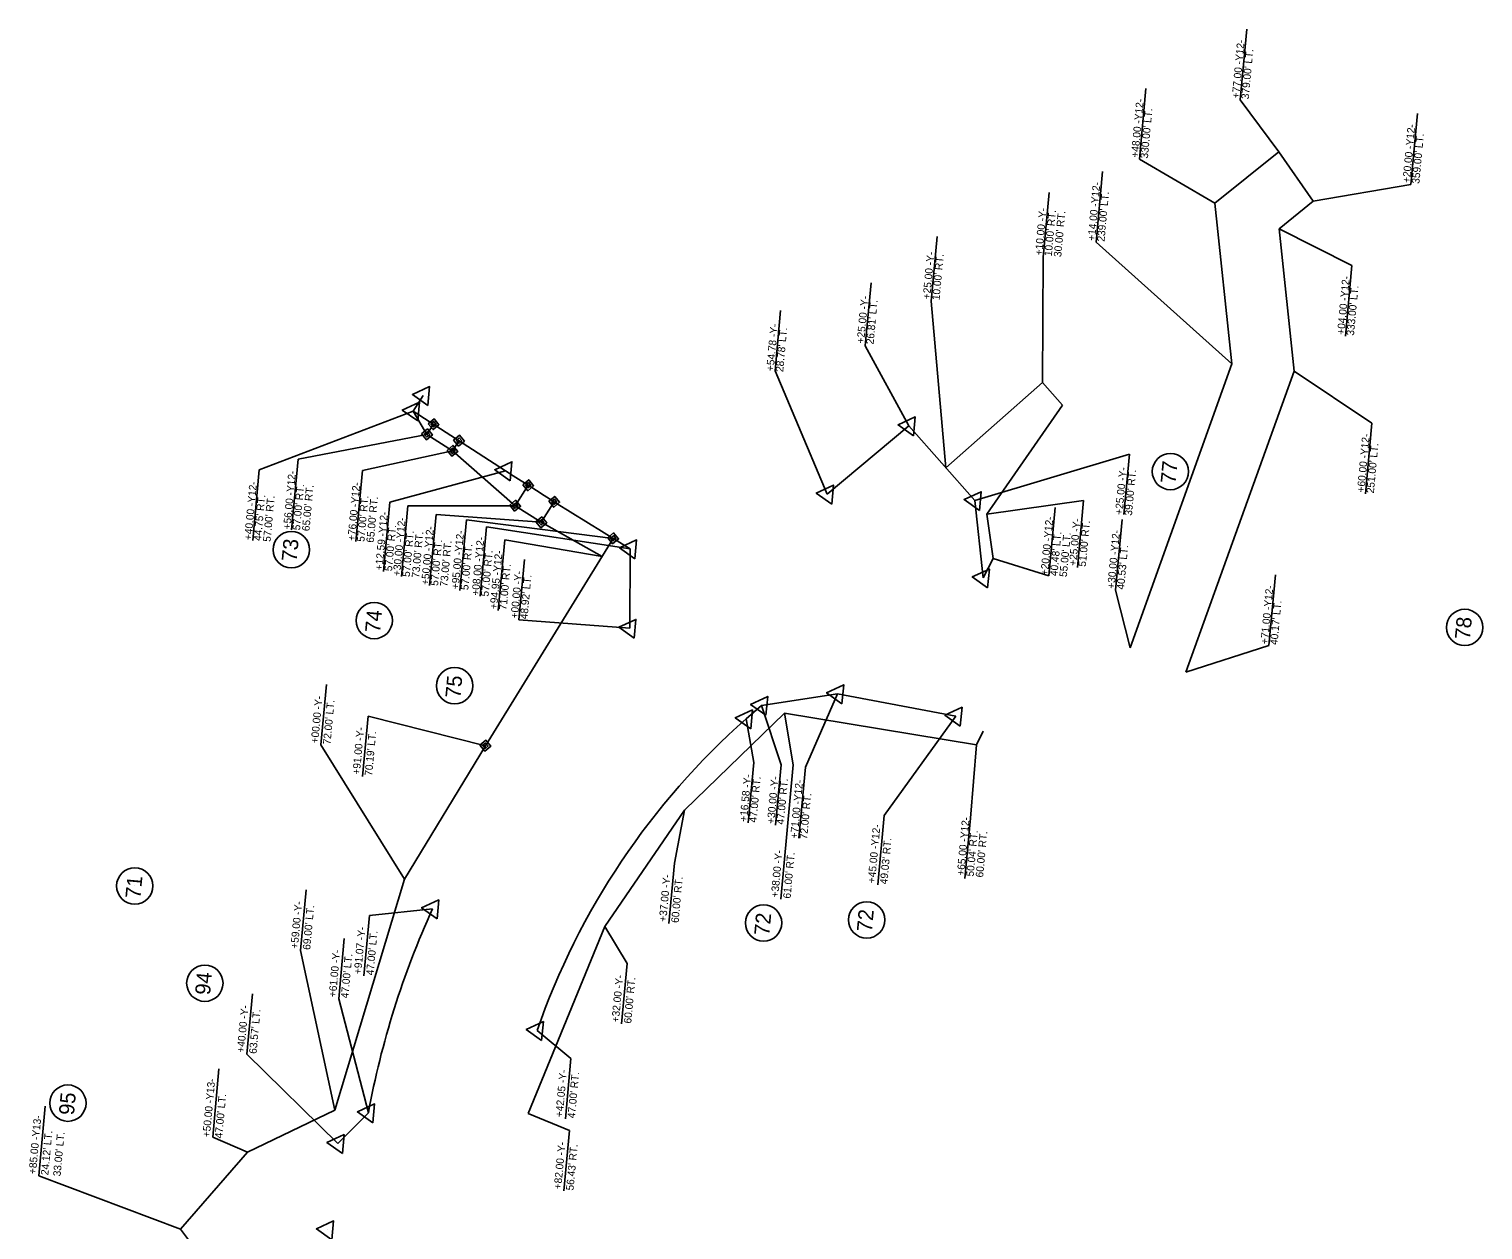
# Model space of a CAD drawing. Extents: x 2010883 to 2014849, y 442000 to 447413.
# Drawn here: x 2012385 to 2013345, y 446621 to 447413 of the extents above; entities that cross this region are included whole.
import ezdxf

# ---------------------------------------------------------------- set-up
doc = ezdxf.new("R2010")
doc.units = 0
for name, color, linetype in [('Prop Easement Construction', 7, 'Continuous'), ('Prop Easement Construction Station Offsets', 7, 'Continuous'), ('Prop Easement Permanent Drainage', 7, 'Continuous'), ('Prop Easement Permanent Drainage Station Offsets', 7, 'Continuous'), ('Prop Easement Permanent Drainage Utility', 7, 'Continuous'), ('Prop Easement Permanent Drainage Utility Station Offsets', 7, 'Continuous'), ('Prop Parcel Number CELL', 7, 'Continuous'), ('Prop Parcel Number Text', 7, 'Continuous'), ('Prop ROW Marker CELL', 7, 'Continuous'), ('Prop ROW Permanent Easement CELL', 7, 'Continuous'), ('Prop ROW RW Lines', 7, 'Continuous'), ('Prop ROW Station Offsets', 7, 'Continuous')]:
    doc.layers.add(name, color=color, linetype=linetype)

msp = doc.modelspace()

# ---------------------------------------------------------------- linework, layer by layer
at = {"layer": 'Prop Easement Construction'}
for p, q in [((2012990.29, 447123.69), (2013054.01, 447179.95)), ((2013067.24, 447164.96), (2013054.01, 447179.95)), ((2012647.94, 447145.67), (2012638.85, 447161.07)), ((2013017.43, 447092.96), (2013067.24, 447164.96)), ((2012706.1, 447098.62), (2012664.74, 447134.81)), ((2013021.47, 447063.84), (2013017.43, 447092.96)), ((2012763.43, 447065.14), (2012723.36, 447087.67)), ((2013014.83, 447050.93), (2013021.47, 447063.84)), ((2012817.86, 446897.73), (2012883.87, 446961.68)), ((2012883.87, 446961.68), (2013010.5, 446940.82)), ((2013010.5, 446940.82), (2013014.83, 446949.79)), ((2012633.05, 446852.19), (2012686.46, 446940.24)), ((2012765.26, 446820.94), (2012817.86, 446897.73)), ((2012587.22, 446699.78), (2012633.05, 446852.19)), ((2012714.74, 446697.6), (2012765.26, 446820.94)), ((2012529.44, 446672.19), (2012587.22, 446699.78)), ((2012485.28, 446621.31), (2012529.44, 446672.19)), ((2012490.71, 446614.28), (2012485.28, 446621.31))]:
    msp.add_line(p, q, dxfattribs=at)
at = {"layer": 'Prop Easement Construction Station Offsets'}
for p, q in [((2013054.57, 447262.58), (2013058.49, 447305.26)), ((2012980.52, 447233.54), (2012984.45, 447276.23)), ((2013054.01, 447179.95), (2013054.57, 447262.58)), ((2012990.29, 447123.69), (2012980.52, 447233.54)), ((2013017.43, 447092.96), (2013081.16, 447102.05)), ((2013077.08, 447057.77), (2013081.16, 447102.05)), ((2012695.02, 447029.42), (2012699.31, 447076.07)), ((2012763.43, 447065.14), (2012699.31, 447076.07)), ((2012577.95, 446940.74), (2012581.61, 446980.57)), ((2012883.87, 446961.68), (2012889.62, 446927.71)), ((2012577.95, 446940.74), (2012633.05, 446852.19)), ((2013010.5, 446940.82), (2013006.51, 446892.51)), ((2012881.48, 446839.09), (2012889.62, 446927.71)), ((2012817.86, 446897.73), (2012811.26, 446862.87)), ((2013002.85, 446852.68), (2013006.51, 446892.51)), ((2012807.6, 446823.03), (2012811.26, 446862.87)), ((2012564.54, 446805.26), (2012568.21, 446845.1)), ((2012765.26, 446820.94), (2012780.02, 446796.52)), ((2012564.54, 446805.26), (2012587.22, 446699.78)), ((2012776.35, 446756.69), (2012780.02, 446796.52)), ((2012506.59, 446682.04), (2012510.72, 446727)), ((2012391.77, 446656.58), (2012395.98, 446702.39)), ((2012714.74, 446697.6), (2012741.93, 446686.34)), ((2012529.44, 446672.19), (2012506.59, 446682.04)), ((2012738.27, 446646.51), (2012741.93, 446686.34)), ((2012485.28, 446621.31), (2012391.77, 446656.58))]:
    msp.add_line(p, q, dxfattribs=at)
at = {"layer": 'Prop Easement Permanent Drainage'}
for p, q in [((2013167.64, 447298.11), (2013209.93, 447332.06)), ((2013232.57, 447299.63), (2013209.93, 447332.06)), ((2013178.99, 447192.14), (2013167.64, 447298.11)), ((2013210.12, 447281.23), (2013232.57, 447299.63)), ((2013220.18, 447187.34), (2013210.12, 447281.23)), ((2013111.91, 447004.78), (2013178.99, 447192.14)), ((2013148.65, 446988.76), (2013220.18, 447187.34)), ((2012652.28, 447152.39), (2012647.94, 447145.67)), ((2012664.74, 447134.81), (2012647.94, 447145.67)), ((2012664.74, 447134.81), (2012669.08, 447141.53)), ((2012706.1, 447098.62), (2012714.71, 447112.1)), ((2012723.36, 447087.67), (2012706.1, 447098.62)), ((2012731.89, 447101.2), (2012723.36, 447087.67))]:
    msp.add_line(p, q, dxfattribs=at)
at = {"layer": 'Prop Easement Permanent Drainage Station Offsets'}
for p, q in [((2013184.54, 447366.35), (2013188.83, 447413.07)), ((2013117.96, 447327.24), (2013122.26, 447373.96)), ((2013209.93, 447332.06), (2013184.54, 447366.35)), ((2013297.08, 447310.56), (2013301.38, 447357.28)), ((2013167.64, 447298.11), (2013117.96, 447327.24)), ((2013089.35, 447272.38), (2013093.64, 447319.11)), ((2013232.57, 447299.63), (2013297.08, 447310.56)), ((2013210.12, 447281.23), (2013258.22, 447257.12)), ((2013178.99, 447192.14), (2013089.35, 447272.38)), ((2013253.92, 447210.39), (2013258.22, 447257.12)), ((2013271.37, 447153.08), (2013220.18, 447187.34)), ((2013267.07, 447106.36), (2013271.37, 447153.08)), ((2012562.93, 447129.4), (2012647.94, 447145.67)), ((2012605.39, 447121.8), (2012664.74, 447134.81)), ((2012558.63, 447082.6), (2012562.93, 447129.4)), ((2012601.09, 447075), (2012605.39, 447121.8)), ((2012631.03, 447051.83), (2012635.33, 447098.63)), ((2012635.33, 447098.63), (2012706.1, 447098.62)), ((2012649.69, 447045.94), (2012654, 447092.74)), ((2012654, 447092.74), (2012723.36, 447087.67)), ((2013102.31, 447042.81), (2013106.6, 447089.53)), ((2013203.47, 447006.29), (2013207.77, 447053.01)), ((2013102.31, 447042.81), (2013111.91, 447004.78)), ((2013203.47, 447006.29), (2013148.65, 446988.76))]:
    msp.add_line(p, q, dxfattribs=at)
at = {"layer": 'Prop Easement Permanent Drainage Utility'}
msp.add_line((2012686.46, 446940.24), (2012770.77, 447077.06), dxfattribs=at)
at = {"layer": 'Prop Easement Permanent Drainage Utility Station Offsets'}
for p, q in [((2012669.68, 447042.71), (2012673.97, 447089.31)), ((2012770.77, 447077.06), (2012673.97, 447089.31)), ((2012605.39, 446919.89), (2012609.06, 446959.72)), ((2012609.06, 446959.72), (2012686.46, 446940.24))]:
    msp.add_line(p, q, dxfattribs=at)
at = {"layer": 'Prop Parcel Number CELL'}
for p, q in [((2013138.47, 447121.13), (2013138.47, 447121.13)), ((2012558.46, 447069.57), (2012558.46, 447069.57)), ((2012613.15, 447022.83), (2012613.15, 447022.83)), ((2013332.62, 447018.29), (2013332.62, 447018.29)), ((2012666.19, 446979.87), (2012666.19, 446979.87)), ((2012455.16, 446847.72), (2012455.16, 446847.72)), ((2012938.05, 446825.33), (2012938.05, 446825.33)), ((2012870, 446823.3), (2012870, 446823.3)), ((2012501.39, 446783.56), (2012501.39, 446783.56)), ((2012411.03, 446704.44), (2012411.03, 446704.44))]:
    msp.add_line(p, q, dxfattribs=at)
for centre in [(2013138.47, 447121.13), (2012558.46, 447069.57), (2012613.15, 447022.83), (2013332.62, 447018.29), (2012666.19, 446979.87), (2012455.16, 446847.72), (2012870, 446823.3), (2012938.05, 446825.33), (2012501.39, 446783.56), (2012411.03, 446704.44)]:
    msp.add_circle(centre, 12, dxfattribs=at)
at = {"layer": 'Prop ROW Marker CELL'}
for p, q in [((2012645.49, 447171.36), (2012645.49, 447171.36)), ((2012638.85, 447161.07), (2012638.85, 447161.07)), ((2012652.28, 447152.39), (2012652.28, 447152.39)), ((2012965.93, 447151.28), (2012965.93, 447151.28)), ((2012647.94, 447145.67), (2012647.94, 447145.67)), ((2012669.08, 447141.53), (2012669.08, 447141.53)), ((2012664.74, 447134.81), (2012664.74, 447134.81)), ((2012699.82, 447121.67), (2012699.82, 447121.67)), ((2012714.71, 447112.1), (2012714.71, 447112.1)), ((2012911.99, 447106.28), (2012911.99, 447106.28)), ((2013009.49, 447101.95), (2013009.49, 447101.95)), ((2012706.1, 447098.62), (2012706.1, 447098.62)), ((2012731.89, 447101.2), (2012731.89, 447101.2)), ((2012723.36, 447087.67), (2012723.36, 447087.67)), ((2012770.77, 447077.06), (2012770.77, 447077.06)), ((2012782.07, 447070.18), (2012782.07, 447070.18)), ((2013014.83, 447050.93), (2013014.83, 447050.93)), ((2012781.69, 447017.72), (2012781.69, 447017.72)), ((2012918.75, 446974.55), (2012918.75, 446974.55)), ((2012858.55, 446958), (2012858.55, 446958)), ((2012868.61, 446966.88), (2012868.61, 446966.88)), ((2012996.81, 446959.74), (2012996.81, 446959.74)), ((2012686.46, 446940.24), (2012686.46, 446940.24)), ((2012651.56, 446832.67), (2012651.56, 446832.67)), ((2012720.57, 446752.32), (2012720.57, 446752.32)), ((2012609.26, 446698), (2012609.26, 446698)), ((2012589.14, 446677.83), (2012589.14, 446677.83)), ((2012582.19, 446620.8), (2012582.19, 446620.8))]:
    msp.add_line(p, q, dxfattribs=at)
for points in [[(2012648.51, 447164.8), (2012638.32, 447172.02), (2012649.65, 447177.25)], [(2012641.86, 447154.52), (2012631.68, 447161.73), (2012643, 447166.96)], [(2012968.94, 447144.73), (2012958.76, 447151.94), (2012970.08, 447157.18)], [(2012702.83, 447115.12), (2012692.65, 447122.33), (2012703.97, 447127.57)], [(2012915, 447099.73), (2012904.82, 447106.94), (2012916.14, 447112.18)], [(2013012.5, 447095.4), (2013002.32, 447102.61), (2013013.64, 447107.85)], [(2012785.08, 447063.63), (2012774.9, 447070.84), (2012786.23, 447076.08)], [(2013017.84, 447044.38), (2013007.66, 447051.59), (2013018.99, 447056.83)], [(2012784.7, 447011.16), (2012774.52, 447018.37), (2012785.84, 447023.61)], [(2012921.76, 446967.99), (2012911.58, 446975.2), (2012922.91, 446980.44)], [(2012871.62, 446960.33), (2012861.44, 446967.54), (2012872.77, 446972.78)], [(2012861.56, 446951.44), (2012851.38, 446958.66), (2012862.71, 446963.89)], [(2012999.83, 446953.19), (2012989.64, 446960.4), (2013000.97, 446965.64)], [(2012654.57, 446826.11), (2012644.39, 446833.33), (2012655.72, 446838.56)], [(2012723.59, 446745.77), (2012713.4, 446752.98), (2012724.73, 446758.22)], [(2012612.27, 446691.45), (2012602.09, 446698.66), (2012613.41, 446703.9)], [(2012592.15, 446671.28), (2012581.97, 446678.49), (2012593.3, 446683.73)], [(2012585.2, 446614.24), (2012575.02, 446621.46), (2012586.34, 446626.69)]]:
    msp.add_lwpolyline(points, close=True, dxfattribs=at)
at = {"layer": 'Prop ROW Permanent Easement CELL'}
for points in [[(2012648.7, 447152.72), (2012652.61, 447155.97), (2012655.87, 447152.06), (2012651.96, 447148.8)], [(2012650.49, 447152.55), (2012652.45, 447154.18), (2012654.08, 447152.22), (2012652.12, 447150.59)], [(2012644.36, 447146), (2012648.27, 447149.25), (2012651.53, 447145.34), (2012647.61, 447142.08)], [(2012646.15, 447145.83), (2012648.11, 447147.46), (2012649.74, 447145.5), (2012647.78, 447143.87)], [(2012665.5, 447141.86), (2012669.41, 447145.12), (2012672.67, 447141.2), (2012668.75, 447137.95)], [(2012667.29, 447141.7), (2012669.25, 447143.32), (2012670.88, 447141.37), (2012668.92, 447139.74)], [(2012661.16, 447135.14), (2012665.07, 447138.4), (2012668.33, 447134.48), (2012664.41, 447131.23)], [(2012662.95, 447134.98), (2012664.91, 447136.6), (2012666.53, 447134.65), (2012664.58, 447133.02)], [(2012711.13, 447112.43), (2012715.04, 447115.69), (2012718.3, 447111.77), (2012714.39, 447108.52)], [(2012712.92, 447112.27), (2012714.88, 447113.89), (2012716.51, 447111.94), (2012714.55, 447110.31)], [(2012702.52, 447098.95), (2012706.43, 447102.2), (2012709.69, 447098.29), (2012705.77, 447095.03)], [(2012728.31, 447101.53), (2012732.22, 447104.79), (2012735.47, 447100.87), (2012731.56, 447097.62)], [(2012730.1, 447101.37), (2012732.06, 447103), (2012733.68, 447101.04), (2012731.73, 447099.41)], [(2012704.31, 447098.78), (2012706.27, 447100.41), (2012707.89, 447098.45), (2012705.94, 447096.83)], [(2012719.77, 447088), (2012723.69, 447091.25), (2012726.94, 447087.34), (2012723.03, 447084.08)], [(2012721.57, 447087.83), (2012723.52, 447089.46), (2012725.15, 447087.5), (2012723.19, 447085.88)], [(2012767.19, 447077.39), (2012771.1, 447080.64), (2012774.36, 447076.73), (2012770.45, 447073.47)], [(2012768.98, 447077.22), (2012770.94, 447078.85), (2012772.57, 447076.89), (2012770.61, 447075.27)], [(2012682.87, 446940.57), (2012686.79, 446943.82), (2012690.04, 446939.91), (2012686.13, 446936.66)], [(2012684.67, 446940.4), (2012686.62, 446942.03), (2012688.25, 446940.08), (2012686.29, 446938.45)]]:
    msp.add_lwpolyline(points, close=True, dxfattribs=at)
at = {"layer": 'Prop ROW RW Lines'}
for p, q in [((2012638.85, 447161.07), (2012645.49, 447171.36)), ((2012638.85, 447161.07), (2012699.82, 447121.67)), ((2012911.99, 447106.28), (2012965.93, 447151.28)), ((2013009.49, 447101.95), (2012965.93, 447151.28)), ((2013014.83, 447050.93), (2013009.49, 447101.95)), ((2012781.69, 447017.72), (2012782.07, 447070.18)), ((2012868.61, 446966.88), (2012918.75, 446974.55)), ((2012918.75, 446974.55), (2012996.81, 446959.74)), ((2012858.55, 446958), (2012868.61, 446966.88)), ((2012589.14, 446677.83), (2012609.26, 446698))]:
    msp.add_line(p, q, dxfattribs=at)
for centre, radius, start, end in [((2014537.56, 449965.84), 3386.24, 237.13174, 238.77371), ((2013181.56, 446592.2), 488, 131.44511, 160.84506), ((2013181.56, 446592.2), 582, 155.59536, 169.52546)]:
    msp.add_arc(centre, radius, start, end, dxfattribs=at)
at = {"layer": 'Prop ROW Station Offsets'}
for p, q in [((2012937.11, 447204.19), (2012940.93, 447245.75)), ((2012877.62, 447187.65), (2012881.28, 447227.49)), ((2012937.11, 447204.19), (2012965.93, 447151.28)), ((2012877.62, 447187.65), (2012911.99, 447106.28)), ((2012537.26, 447122.37), (2012638.85, 447161.07)), ((2013009.49, 447101.95), (2013111.38, 447132.7)), ((2013107.72, 447092.87), (2013111.38, 447132.7)), ((2012532.96, 447075.56), (2012537.26, 447122.37)), ((2012623.52, 447100.99), (2012699.82, 447121.67)), ((2012619.31, 447055.18), (2012623.52, 447100.99)), ((2013058.26, 447052.26), (2013062.42, 447097.51)), ((2012683.03, 447038.9), (2012687.24, 447084.71)), ((2012687.24, 447084.71), (2012782.07, 447070.18)), ((2013021.47, 447063.84), (2013058.26, 447052.26)), ((2012708.65, 447023.29), (2012712.32, 447063.12)), ((2012708.65, 447023.29), (2012781.69, 447017.72)), ((2012897.64, 446926.14), (2012918.75, 446974.55)), ((2012863.57, 446929.27), (2012858.55, 446958)), ((2012881.53, 446927.62), (2012868.61, 446966.88)), ((2012949.55, 446894.32), (2012996.81, 446959.74)), ((2012859.91, 446889.44), (2012863.57, 446929.27)), ((2012877.86, 446887.79), (2012881.53, 446927.62)), ((2012893.34, 446879.34), (2012897.64, 446926.14)), ((2012945.33, 446848.51), (2012949.55, 446894.32)), ((2012606.34, 446788.46), (2012610, 446828.3)), ((2012610, 446828.3), (2012651.56, 446832.67)), ((2012589.7, 446773.32), (2012593.36, 446813.15)), ((2012529.12, 446736.67), (2012532.78, 446776.5)), ((2012589.7, 446773.32), (2012609.26, 446698)), ((2012742.92, 446733.97), (2012720.57, 446752.32)), ((2012529.12, 446736.67), (2012589.14, 446677.83)), ((2012739.26, 446694.13), (2012742.92, 446733.97))]:
    msp.add_line(p, q, dxfattribs=at)

# ---------------------------------------------------------------- texts
at = {"layer": 'Prop Easement Construction Station Offsets'}
for s, p in [('+10.00 -Y-', (2013053.94, 447263.63)), ("10.00' RT.", (2013060.17, 447263.06)), ("30.00' RT.", (2013066.39, 447262.49)), ('+25.00 -Y-', (2012979.9, 447234.6)), ("10.00' RT.", (2012986.12, 447234.03)), ('+25.00 -Y-', (2013076.38, 447058.79)), ("51.00' RT.", (2013082.61, 447058.22)), ('+94.95 -Y12-', (2012694.26, 447030.15)), ("71.00' RT.", (2012700.48, 447029.58)), ('+00.00 -Y-', (2012576.19, 446941.63)), ("72.00' LT.", (2012584.29, 446940.88)), ('+65.00 -Y12-', (2013002.4, 446854.34)), ("50.04' RT.", (2013008.62, 446853.77)), ("60.00' RT.", (2013014.84, 446853.19)), ('+38.00 -Y-', (2012879.72, 446839.98)), ("61.00' RT.", (2012887.81, 446839.24)), ('+37.00 -Y-', (2012805.84, 446823.92)), ("60.00' RT.", (2012813.93, 446823.18)), ('+59.00 -Y-', (2012562.79, 446806.15)), ("69.00' LT.", (2012570.88, 446805.41)), ('+32.00 -Y-', (2012774.6, 446757.58)), ("60.00' RT.", (2012782.69, 446756.83)), ('+50.00 -Y13-', (2012504.73, 446681.78)), ("47.00' LT.", (2012512.82, 446681.03)), ('+85.00 -Y13-', (2012390.01, 446657.47)), ("24.12' LT.", (2012398.1, 446656.72)), ("33.00' LT.", (2012406.19, 446655.98)), ('+82.00 -Y-', (2012736.51, 446647.39)), ("56.43' RT.", (2012744.6, 446646.65))]:
    msp.add_text(s, height=5, rotation=84.74666, dxfattribs=at).set_placement(p)
at = {"layer": 'Prop Easement Permanent Drainage Station Offsets'}
for s, p in [('+77.00 -Y12-', (2013183.89, 447367.18)), ("379.00' LT.", (2013190.12, 447366.61)), ('+48.00 -Y12-', (2013117.32, 447328.07)), ("330.00' LT.", (2013123.55, 447327.5)), ('+20.00 -Y12-', (2013296.44, 447311.39)), ("359.00' LT.", (2013302.66, 447310.82)), ('+14.00 -Y12-', (2013088.7, 447273.22)), ("239.00' LT.", (2013094.93, 447272.65)), ('+04.00 -Y12-', (2013253.28, 447211.23)), ("333.00' LT.", (2013259.51, 447210.66)), ('+60.00 -Y12-', (2013266.43, 447107.19)), ("251.00' LT.", (2013272.65, 447106.62)), ('+56.00 -Y12-', (2012557.93, 447082.79)), ("57.00' RT.", (2012564.16, 447082.22)), ("65.00' RT.", (2012570.38, 447081.65)), ('+76.00 -Y12-', (2012600.4, 447075.19)), ("57.00' RT.", (2012606.62, 447074.62)), ("65.00' RT.", (2012612.84, 447074.05)), ('+30.00 -Y12-', (2012630.33, 447052.02)), ('+50.00 -Y12-', (2012649, 447046.13)), ("57.00' RT.", (2012636.56, 447051.45)), ("73.00' RT.", (2012642.78, 447050.87)), ("57.00' RT.", (2012655.22, 447045.56)), ("73.00' RT.", (2012661.45, 447044.98)), ('+30.00 -Y12-', (2013101.66, 447043.65)), ("40.53' LT.", (2013107.89, 447043.07)), ('+71.00 -Y12-', (2013202.83, 447007.12)), ("40.17' LT.", (2013209.06, 447006.55))]:
    msp.add_text(s, height=5, rotation=84.74666, dxfattribs=at).set_placement(p)
at = {"layer": 'Prop Easement Permanent Drainage Utility Station Offsets'}
for s, p in [('+95.00 -Y12-', (2012668.91, 447043.31)), ("57.00' RT.", (2012675.14, 447042.74)), ('+91.00 -Y-', (2012603.66, 446920.97)), ("70.19' LT.", (2012611.75, 446920.22))]:
    msp.add_text(s, height=5, rotation=84.74666, dxfattribs=at).set_placement(p)
at = {"layer": 'Prop Parcel Number Text'}
for s, p in [('77', (2013141.87, 447112.86)), ('73', (2012561.96, 447061.51)), ('74', (2012616.99, 447014.52)), ('78', (2013336.02, 447010.02)), ('75', (2012669.98, 446971.36)), ('71', (2012458.88, 446839.16)), ('72', (2012873.76, 446814.71)), ('72', (2012941.44, 446817.07)), ('94', (2012504.81, 446775.52)), ('95', (2012414.98, 446696.25))]:
    msp.add_text(s, height=10, rotation=84.74666, dxfattribs=at).set_placement(p)
at = {"layer": 'Prop ROW Station Offsets'}
for s, p in [('+25.00 -Y-', (2012936.35, 447205.49)), ("26.81' LT.", (2012942.58, 447204.91)), ('+54.78 -Y-', (2012876.7, 447187.22)), ("28.78' LT.", (2012882.93, 447186.65)), ('+25.00 -Y-', (2013106.8, 447092.44)), ("39.00' RT.", (2013113.03, 447091.86)), ('+40.00 -Y12-', (2012532.26, 447075.75)), ("44.75' RT.", (2012538.49, 447075.18)), ("57.00' RT.", (2012544.71, 447074.61)), ('+12.59 -Y12-', (2012618.63, 447055.77)), ("57.00' RT.", (2012624.85, 447055.19)), ('+20.00 -Y12-', (2013057.64, 447052.57)), ('+08.00 -Y12-', (2012682.31, 447039.07)), ("40.48' LT.", (2013063.87, 447051.99)), ("55.00' LT.", (2013070.09, 447051.42)), ("57.00' RT.", (2012688.53, 447038.49)), ('+00.00 -Y-', (2012707.98, 447024.08)), ("48.92' LT.", (2012714.2, 447023.51)), ('+16.58 -Y-', (2012859.12, 446889.91)), ('+30.00 -Y-', (2012877.14, 446888.58)), ("47.00' RT.", (2012865.34, 446889.33)), ("47.00' RT.", (2012883.37, 446888.01)), ('+71.00 -Y12-', (2012892.51, 446878.89)), ("72.00' RT.", (2012898.74, 446878.32)), ('+45.00 -Y12-', (2012943.58, 446849.42)), ("49.03' RT.", (2012951.67, 446848.67)), ('+91.07 -Y-', (2012604.58, 446789.35)), ("47.00' LT.", (2012612.67, 446788.61)), ('+61.00 -Y-', (2012587.94, 446774.21)), ("47.00' LT.", (2012596.03, 446773.46)), ('+40.00 -Y-', (2012527.37, 446737.56)), ("63.57' LT.", (2012535.46, 446736.82)), ('+42.05 -Y-', (2012737.51, 446695.02)), ("47.00' RT.", (2012745.6, 446694.28))]:
    msp.add_text(s, height=5, rotation=84.74666, dxfattribs=at).set_placement(p)

doc.saveas('drawing.dxf')
